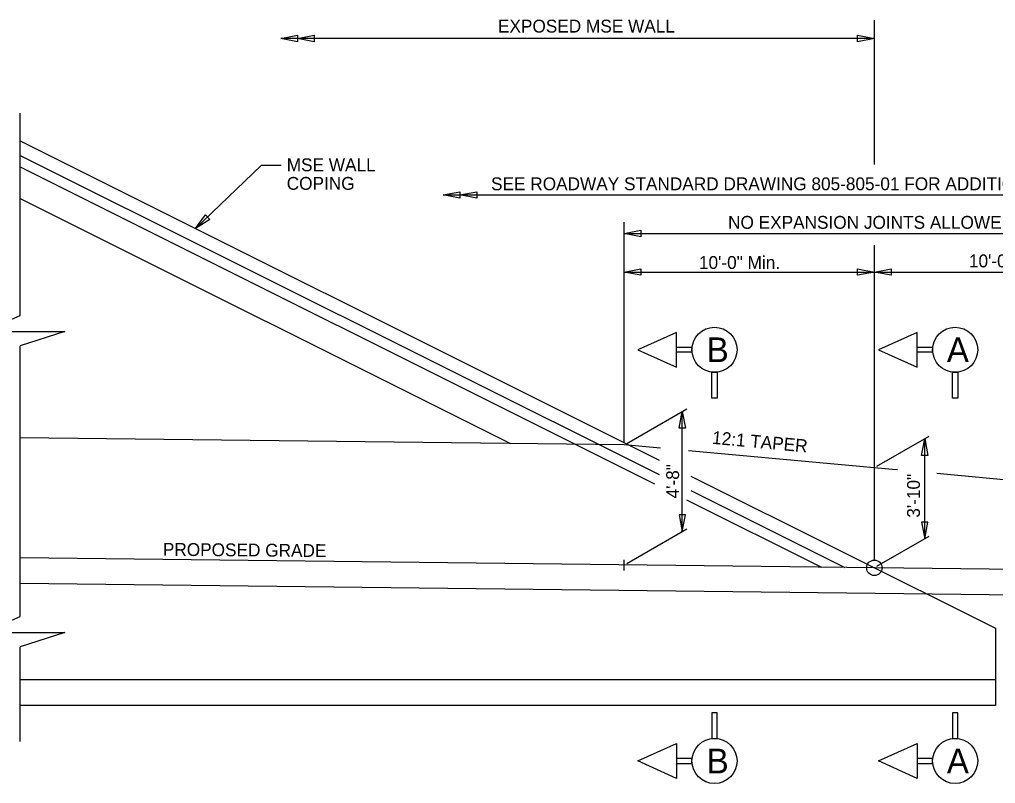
# Model space of a CAD drawing. Extents: x 96 to 240, y 601 to 689.
# Drawn here: x 115.15 to 153.07, y 627.04 to 656.74 of the extents above; entities that cross this region are included whole.
import ezdxf

# ---------------------------------------------------------------- set-up
doc = ezdxf.new("R2010")
doc.units = 0
for name, color, linetype in [('BR_AUTO DIMENSION', 7, 'Continuous'), ('BR_CONCRETE', 7, 'Continuous'), ('BR_TEXT', 7, 'Continuous'), ('Default', 7, 'Continuous')]:
    doc.layers.add(name, color=color, linetype=linetype)

msp = doc.modelspace()

# ---------------------------------------------------------------- linework, layer by layer
at = {"layer": 'BR_AUTO DIMENSION'}
for p, q in [((148.363, 651.104), (148.363, 656.712)), ((148.363, 655.999), (125.305, 655.999)), ((115.181, 645.233), (115.181, 653.093)), ((124.544, 651.065), (121.988, 648.614)), ((125.323, 651.065), (124.544, 651.065)), ((131.614, 649.919), (159.066, 649.919)), ((138.644, 640.31), (138.644, 648.862)), ((138.644, 648.421), (161.649, 648.421)), ((148.363, 635.727), (148.363, 647.961)), ((138.644, 646.922), (161.649, 646.922)), ((113.78, 644.618), (115.181, 645.233)), ((113.78, 644.618), (116.921, 644.618)), ((116.921, 644.618), (115.181, 644.053)), ((115.181, 633.529), (115.181, 644.053)), ((138.744, 640.264), (141.074, 641.604)), ((140.899, 636.837), (140.899, 641.504)), ((148.464, 639.375), (150.491, 640.541)), ((150.316, 636.551), (150.316, 640.44)), ((138.744, 635.597), (141.074, 636.937)), ((148.464, 635.485), (150.491, 636.651)), ((138.644, 635.324), (138.644, 635.735)), ((113.78, 632.914), (115.181, 633.529)), ((113.78, 632.914), (116.921, 632.914)), ((116.921, 632.914), (115.181, 632.349)), ((115.181, 628.678), (115.181, 632.349))]:
    msp.add_line(p, q, dxfattribs=at)
for points in [[(125.955, 655.874), (125.305, 655.999), (125.955, 656.124)], [(126.605, 655.874), (125.955, 655.999), (126.605, 656.124)], [(147.713, 656.124), (148.363, 655.999), (147.713, 655.874)], [(132.264, 649.794), (131.614, 649.919), (132.264, 650.044)], [(132.914, 649.794), (132.264, 649.919), (132.914, 650.044)], [(122.547, 648.97), (121.988, 648.614), (122.375, 649.152)], [(139.294, 648.296), (138.644, 648.421), (139.294, 648.546)], [(139.294, 646.797), (138.644, 646.922), (139.294, 647.047)], [(147.713, 647.047), (148.363, 646.922), (147.713, 646.797)], [(149.013, 646.797), (148.363, 646.922), (149.013, 647.047)], [(140.774, 640.854), (140.899, 641.504), (141.024, 640.854)], [(150.191, 639.79), (150.316, 640.44), (150.441, 639.79)], [(140.774, 637.487), (140.899, 636.837), (141.024, 637.487)], [(150.191, 637.201), (150.316, 636.551), (150.441, 637.201)]]:
    msp.add_lwpolyline(points, close=True, dxfattribs=at)
msp.add_circle((148.363, 635.427), 0.3, dxfattribs=at)
at = {"layer": 'BR_CONCRETE'}
for p, q in [((115.181, 652.018), (138.808, 640.204)), ((115.181, 651.459), (140.001, 639.049)), ((115.181, 651.012), (139.822, 638.691)), ((115.181, 649.782), (134.231, 640.257)), ((138.644, 640.206), (115.181, 640.477)), ((140.058, 640.077), (138.644, 640.206)), ((138.808, 640.204), (140.001, 639.608)), ((149.066, 639.252), (141.138, 639.978)), ((149.262, 639.234), (149.066, 639.252)), ((141.237, 638.99), (153.066, 633.076)), ((156.23, 638.573), (150.794, 639.088)), ((141.058, 638.073), (146.303, 635.451)), ((141.237, 638.431), (147.219, 635.44)), ((161.649, 634.273), (115.181, 634.81)), ((153.066, 633.076), (153.066, 630.076)), ((153.066, 631.076), (115.181, 631.076)), ((153.066, 631.076), (115.181, 631.076)), ((153.066, 630.076), (115.181, 630.076))]:
    msp.add_line(p, q, dxfattribs=at)
at = {"layer": 'BR_TEXT'}
for points in [[(140.675, 644.577), (139.174, 643.902), (140.675, 643.226)], [(150.023, 644.577), (148.521, 643.902), (150.023, 643.226)], [(141.275, 643.802), (140.675, 643.802), (140.675, 644.002), (141.275, 644.002)], [(150.623, 643.802), (150.023, 643.802), (150.023, 644.002), (150.623, 644.002)], [(142.251, 642.025), (142.051, 642.025), (142.051, 643.026), (142.251, 643.026)], [(151.599, 642.025), (151.399, 642.025), (151.399, 643.026), (151.599, 643.026)], [(142.251, 629.794), (142.051, 629.794), (142.051, 628.794), (142.251, 628.794)], [(151.599, 629.794), (151.399, 629.794), (151.399, 628.794), (151.599, 628.794)], [(140.675, 627.242), (139.174, 627.918), (140.675, 628.593)], [(150.023, 627.242), (148.521, 627.918), (150.023, 628.593)], [(141.275, 628.018), (140.675, 628.018), (140.675, 627.818), (141.275, 627.818)], [(150.623, 628.018), (150.023, 628.018), (150.023, 627.818), (150.623, 627.818)]]:
    msp.add_lwpolyline(points, close=True, dxfattribs=at)
for centre in [(142.151, 643.902), (151.499, 643.902), (142.151, 627.918), (151.499, 627.918)]:
    msp.add_circle(centre, 0.876, dxfattribs=at)
at = {"layer": 'Default'}
msp.add_line((168.631, 635.193), (115.181, 635.81), dxfattribs=at)

# ---------------------------------------------------------------- texts
at = {"layer": 'BR_AUTO DIMENSION'}
for s, rotation, p in [('EXPOSED MSE WALL', 360, (133.741, 656.232)), ('SEE ROADWAY STANDARD DRAWING 805-805-01 FOR ADDITIONAL DETAILS', 360, (133.472, 650.102)), ('NO EXPANSION JOINTS ALLOWED IN BARRIER', 360, (142.679, 648.604)), ('10\'-0" Min.', 360, (141.548, 647.044)), ('10\'-0" Min.', 360, (152.036, 647.105)), ('12:1 TAPER', 354.7714, (142.043, 640.247)), ('4\'-8"', 90, (140.776, 638.124)), ('3\'-10"', 90, (150.132, 637.374)), ('PROPOSED GRADE', 359.5314, (120.721, 635.895))]:
    msp.add_text(s, height=0.5, rotation=rotation, dxfattribs=at).set_placement(p)
for s, p in [('MSE WALL', (125.534, 650.84)), ('COPING', (125.534, 650.119))]:
    msp.add_text(s, height=0.5, dxfattribs=at).set_placement(p)
at = {"layer": 'BR_TEXT'}
for s, p in [('B', (141.849, 643.422)), ('A', (151.178, 643.422)), ('B', (141.849, 627.438)), ('A', (151.178, 627.438))]:
    msp.add_text(s, height=0.96, dxfattribs=at).set_placement(p)

doc.saveas('drawing.dxf')
